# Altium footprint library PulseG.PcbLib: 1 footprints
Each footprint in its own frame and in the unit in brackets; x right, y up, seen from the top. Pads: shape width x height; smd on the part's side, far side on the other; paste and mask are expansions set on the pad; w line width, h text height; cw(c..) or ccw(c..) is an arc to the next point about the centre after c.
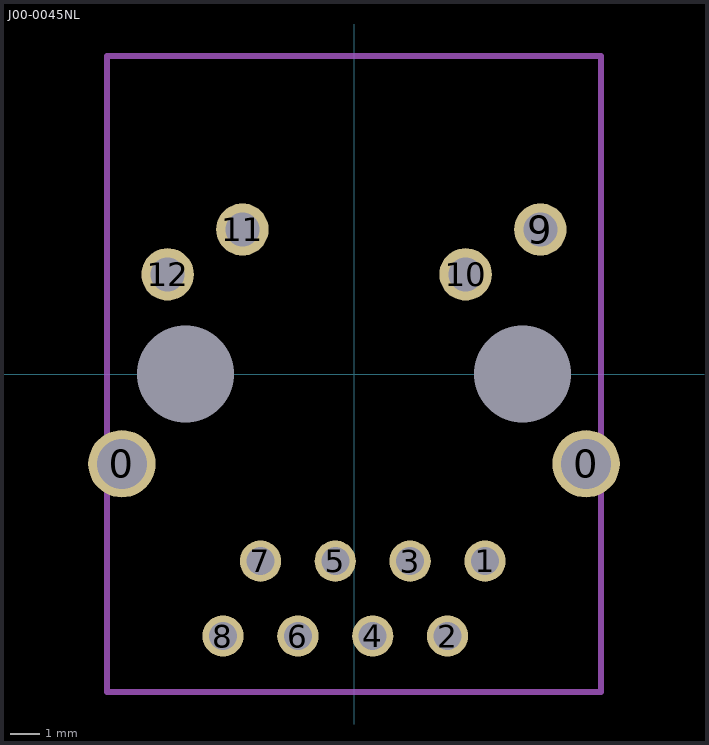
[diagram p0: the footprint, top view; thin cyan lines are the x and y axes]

## J00-0045NL [mil]
pads (16):
  round 90 hole 66.93: 0(-310,-120) 0(310,-120)
  round 55.12 hole 37.4: 1(175,-250) 2(125,-350) 3(75,-250) 4(25,-350) 5(-25,-250) 6(-75,-350) 7(-125,-250) 8(-175,-350)
  round 70 hole 45: 9(249,193) 10(149,133) 11(-149,193) 12(-249,133)
  round 0 hole 130: G(-225,0) G(225,0)
Mechanical 13:
  lines w7.87: -330,-425 -330,425 330,425 330,-425 -330,-425
3D body: height 560, standoff 0, extent -330,-425 330,425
